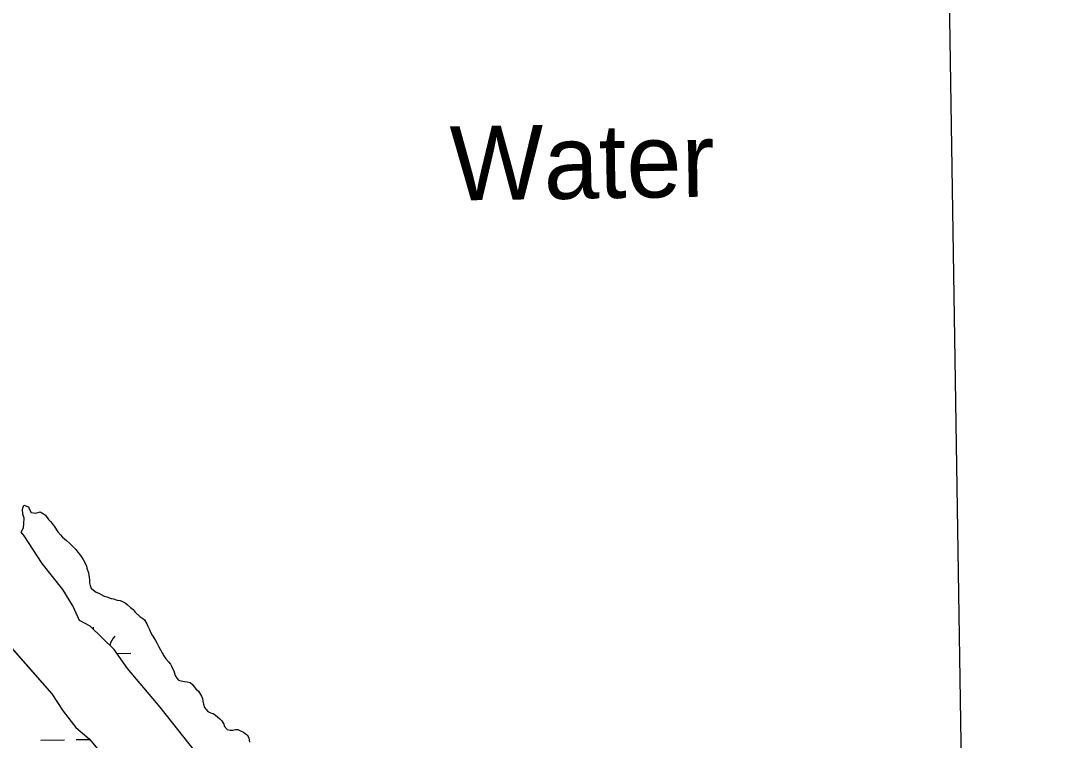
# Model space of a CAD drawing. Extents: x 3807117 to 3845308, y 337856 to 363736.
# Drawn here: x 3841805 to 3843194, y 351687 to 352657 of the extents above; entities that cross this region are included whole.
import ezdxf

# ---------------------------------------------------------------- set-up
doc = ezdxf.new("R2010")
doc.units = 0
for name, color, linetype in [('V-GRID-FRAM', 7, 'Continuous'), ('V-RIVR-IDEN', 7, 'Continuous'), ('V-TOPO-SHOR', 7, 'Continuous'), ('V-WETL-SWMP', 7, 'Continuous')]:
    doc.layers.add(name, color=color, linetype=linetype)

msp = doc.modelspace()

# ---------------------------------------------------------------- linework, layer by layer
at = {"layer": 'V-GRID-FRAM'}
msp.add_lwpolyline([(3811100.6, 361461.9), (3842914.2, 361938.5), (3843194.5, 343758.3), (3811365, 343281.4), (3811100.6, 361461.9)], dxfattribs=at)
at = {"layer": 'V-TOPO-SHOR'}
for p, q in [((3841712.3, 351902), (3841846.8, 351749.7)), ((3841846.8, 351749.7), (3841862.1, 351725.9)), ((3841862.1, 351725.9), (3841879.1, 351703.9)), ((3841879.1, 351703.9), (3841897, 351689)), ((3841897, 351689), (3841917.7, 351664.3))]:
    msp.add_line(p, q, dxfattribs=at)
for points in [[(3841805.1, 351967.4), (3841808.2, 351973.4), (3841808.9, 351979.3), (3841809.3, 351986.5), (3841807.6, 351992), (3841807.2, 351998.7), (3841808.7, 352003.9), (3841815.1, 352001.6), (3841815.9, 351999.2), (3841818.7, 351994.1), (3841825.1, 351993.3), (3841831, 351995), (3841835.5, 351992.3), (3841837.9, 351990.4), (3841842.3, 351984.5), (3841844.7, 351981.7), (3841847.1, 351979.4), (3841849.9, 351975.4), (3841854.8, 351967.9), (3841858.4, 351964), (3841860.8, 351960.9), (3841866.4, 351956.2), (3841870.4, 351952.6), (3841874.8, 351948.3), (3841878.8, 351944), (3841881.6, 351940.4), (3841884, 351937.7), (3841886, 351934.5), (3841888.8, 351930.6), (3841893.2, 351922.3), (3841893.7, 351919.1), (3841896.1, 351912.8), (3841897.4, 351903.3), (3841897.4, 351899.4), (3841898.2, 351895.4), (3841899.8, 351892.2), (3841903, 351889.1), (3841906.6, 351886.8), (3841910.2, 351885.2), (3841917.4, 351881.3), (3841921, 351880.5), (3841926.5, 351878.2), (3841929.7, 351877.4), (3841934.9, 351875.9), (3841938.8, 351875.5), (3841942, 351874), (3841945.6, 351872), (3841948.4, 351870.1), (3841952.8, 351865.8), (3841956.4, 351863), (3841959.2, 351859.5), (3841965.2, 351853.6), (3841969.2, 351851.2), (3841971.6, 351849.3), (3841974.8, 351843.8), (3841976, 351840.6), (3841978.4, 351836.3), (3841980.1, 351831.9), (3841981.7, 351828.4), (3841984.1, 351825.2), (3841986.5, 351821.3), (3841988.1, 351818.1), (3841990.9, 351813), (3841997.8, 351800.8), (3842000.2, 351796.8), (3842003.8, 351792.5), (3842006.6, 351789.7), (3842008.2, 351787), (3842009.4, 351783.8), (3842011.1, 351780.7), (3842013.1, 351774.3), (3842015.1, 351770.4), (3842017.5, 351768), (3842021.1, 351766.9), (3842025.5, 351766.1), (3842029, 351765.8), (3842033, 351764.6), (3842036.2, 351762.3), (3842038.6, 351759.1), (3842041, 351756.4), (3842044.2, 351753.2), (3842048.6, 351746.5), (3842049.9, 351743), (3842050.3, 351739.8), (3842051.1, 351735.4), (3842052.7, 351731.1), (3842056.8, 351725.6), (3842060.7, 351724), (3842064.3, 351722.9), (3842067.5, 351720.9), (3842069.9, 351718.6), (3842073.1, 351715.8), (3842075.9, 351713.1), (3842078.7, 351708.7), (3842079.5, 351705.6), (3842083.1, 351701.2), (3842087.1, 351700.5), (3842090.7, 351700.5), (3842094.2, 351701.3), (3842097.4, 351701.4), (3842101, 351699.8)], [(3841898.3, 351840.7), (3841884, 351848.6), (3841875, 351868), (3841861.5, 351890.1), (3841833.6, 351925.3), (3841809.4, 351962.4), (3841805.1, 351967.4)], [(3842469.7, 351210.4), (3842459.5, 351212.2), (3842417.6, 351237.6), (3842348.8, 351287.5), (3842324.6, 351313), (3842279.7, 351373), (3842255.5, 351398.5), (3842233.1, 351424.9), (3842200.7, 351476.1), (3842164.9, 351510.4), (3842096.6, 351600.3), (3841992.5, 351731.5), (3841948.5, 351783.5), (3841930.5, 351809.1), (3841898.3, 351840.7)], [(3842101, 351699.8), (3842105, 351697.9), (3842107.4, 351695.9), (3842110.2, 351694), (3842112.2, 351690), (3842113, 351684.5)]]:
    msp.add_lwpolyline(points, dxfattribs=at)
at = {"layer": 'V-WETL-SWMP'}
for p, q in [((3841902.8, 351836.3), (3841902.7, 351839.5)), ((3841934.1, 351804), (3841953.2, 351804.3)), ((3841831.6, 351687), (3841863.6, 351687.5)), ((3841879.6, 351687.7), (3841897.8, 351688))]:
    msp.add_line(p, q, dxfattribs=at)
for points in [[(3841805.1, 351967.4), (3841808.2, 351973.4), (3841808.9, 351979.3), (3841809.3, 351986.5), (3841807.6, 351992), (3841807.2, 351998.7), (3841808.7, 352003.9), (3841815.1, 352001.6), (3841815.9, 351999.2), (3841818.7, 351994.1), (3841825.1, 351993.3), (3841831, 351995), (3841835.5, 351992.3), (3841837.9, 351990.4), (3841842.3, 351984.5), (3841844.7, 351981.7), (3841847.1, 351979.4), (3841849.9, 351975.4), (3841854.8, 351967.9), (3841858.4, 351964), (3841860.8, 351960.9), (3841866.4, 351956.2), (3841870.4, 351952.6), (3841874.8, 351948.3), (3841878.8, 351944), (3841881.6, 351940.4), (3841884, 351937.7), (3841886, 351934.5), (3841888.8, 351930.6), (3841893.2, 351922.3), (3841893.7, 351919.1), (3841896.1, 351912.8), (3841897.4, 351903.3), (3841897.4, 351899.4), (3841898.2, 351895.4), (3841899.8, 351892.2), (3841903, 351889.1), (3841906.6, 351886.8), (3841910.2, 351885.2), (3841917.4, 351881.3), (3841921, 351880.5), (3841926.5, 351878.2), (3841929.7, 351877.4), (3841934.9, 351875.9), (3841938.8, 351875.5), (3841942, 351874), (3841945.6, 351872), (3841948.4, 351870.1), (3841952.8, 351865.8), (3841956.4, 351863), (3841959.2, 351859.5), (3841965.2, 351853.6), (3841969.2, 351851.2), (3841971.6, 351849.3), (3841974.8, 351843.8), (3841976, 351840.6), (3841978.4, 351836.3), (3841980.1, 351831.9), (3841981.7, 351828.4), (3841984.1, 351825.2), (3841986.5, 351821.3), (3841988.1, 351818.1), (3841990.9, 351813), (3841997.8, 351800.8), (3842000.2, 351796.8), (3842003.8, 351792.5), (3842006.6, 351789.7), (3842008.2, 351787), (3842009.4, 351783.8), (3842011.1, 351780.7), (3842013.1, 351774.3), (3842015.1, 351770.4), (3842017.5, 351768), (3842021.1, 351766.9), (3842025.5, 351766.1), (3842029, 351765.8), (3842033, 351764.6), (3842036.2, 351762.3), (3842038.6, 351759.1), (3842041, 351756.4), (3842044.2, 351753.2), (3842048.6, 351746.5), (3842049.9, 351743), (3842050.3, 351739.8), (3842051.1, 351735.4), (3842052.7, 351731.1), (3842056.8, 351725.6), (3842060.7, 351724), (3842064.3, 351722.9), (3842067.5, 351720.9), (3842069.9, 351718.6), (3842073.1, 351715.8), (3842075.9, 351713.1), (3842078.7, 351708.7), (3842079.5, 351705.6), (3842083.1, 351701.2), (3842087.1, 351700.5), (3842090.7, 351700.5), (3842094.2, 351701.3), (3842097.4, 351701.4), (3842101, 351699.8)], [(3841898.3, 351840.7), (3841884, 351848.6), (3841875, 351868), (3841861.5, 351890.1), (3841833.6, 351925.3), (3841809.4, 351962.4), (3841805.1, 351967.4)], [(3841712.3, 351902), (3841846.8, 351749.7), (3841862.1, 351725.9), (3841879.1, 351703.9), (3841897, 351689), (3841917.7, 351664.3)], [(3842096.6, 351600.3), (3841992.5, 351731.5), (3841948.5, 351783.5), (3841930.5, 351809.1), (3841898.3, 351840.7)], [(3842101, 351699.8), (3842105, 351697.9), (3842107.4, 351695.9), (3842110.2, 351694), (3842112.2, 351690), (3842113, 351684.5)]]:
    msp.add_lwpolyline(points, dxfattribs=at)
msp.add_arc((3841958.5, 351804.8), 35.2, 140.0865, 163.5412, dxfattribs=at)

# ---------------------------------------------------------------- texts
at = {"layer": 'V-RIVR-IDEN'}
msp.add_text('Water', height=100, rotation=0.8756, dxfattribs=at).set_placement((3842384.3, 352414.7))

doc.saveas('drawing.dxf')
